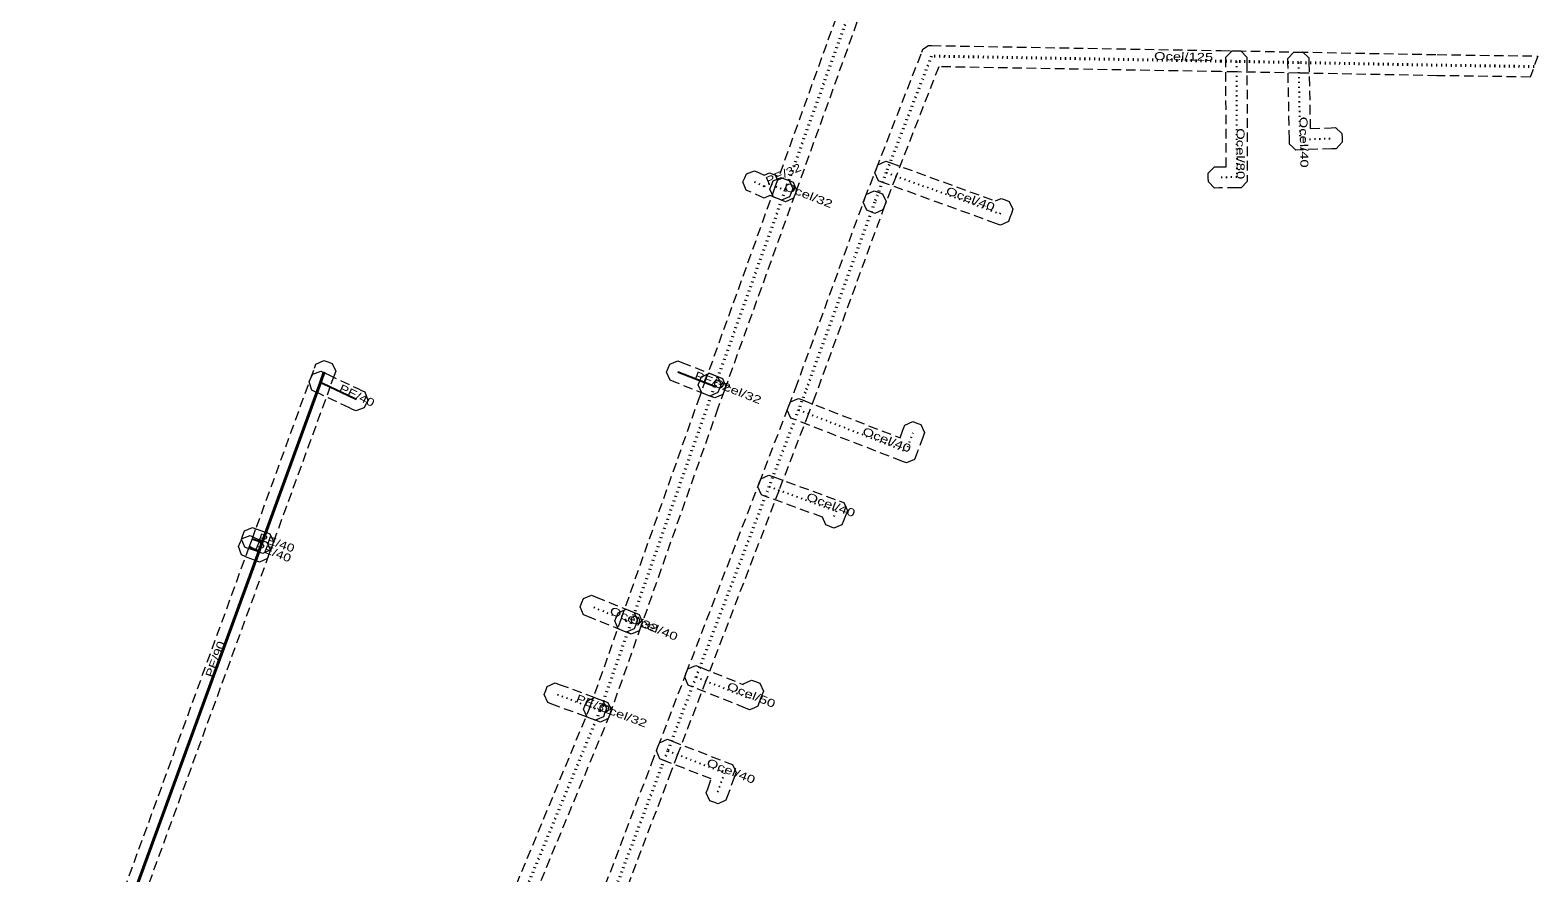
# Model space of a CAD drawing. Extents: x -644301 to -644150, y -1042432 to -1042139.
# Drawn here: x -644293 to -644149.7, y -1042284.7 to -1042204.6 of the extents above; entities that cross this region are included whole.
import ezdxf

# ---------------------------------------------------------------- set-up
doc = ezdxf.new("R2010")
doc.units = 0
doc.header["$LTSCALE"] = 0.3
doc.linetypes.add('DOTTED', pattern=[1.5, 0.3, -1.2])
doc.linetypes.add('MEDIUM_DASHED', pattern=[4.5, 3, -1.5])
for name, color, linetype, lineweight in [('1', 7, 'MEDIUM_DASHED', 13), ('14', 7, 'Continuous', 25), ('18', 7, 'DOTTED', 25)]:
    doc.layers.add(name, color=color, linetype=linetype, lineweight=lineweight)
doc.layers.add('20', color=7, linetype='Continuous')

msp = doc.modelspace()

# ---------------------------------------------------------------- linework, layer by layer
at = {"layer": '1'}
for points in [[(-644250.393, -1042294.532), (-644239.756, -1042268.927), (-644236.811, -1042260.588), (-644229.493, -1042239.868), (-644228.876, -1042238.156), (-644222.16, -1042219.521), (-644214.681, -1042198.769), (-644215.428, -1042198.11), (-644215.739, -1042197.836), (-644215.791, -1042197.01), (-644215.517, -1042196.699), (-644215.243, -1042196.388), (-644214.417, -1042196.336), (-644214.106, -1042196.61), (-644212.849, -1042197.718), (-644212.618, -1042197.921), (-644212.465, -1042198.517), (-644212.569, -1042198.807), (-644220.278, -1042220.199), (-644226.994, -1042238.834), (-644227.609, -1042240.54), (-644234.925, -1042261.254), (-644237.888, -1042269.645), (-644248.531, -1042295.264)], [(-644242.633, -1042297.224), (-644233.926, -1042274.319), (-644233.312, -1042272.722), (-644230.622, -1042265.714), (-644223.677, -1042247.626), (-644220.88, -1042240.342), (-644220.242, -1042238.679), (-644213.656, -1042220.626), (-644213.514, -1042220.237), (-644212.763, -1042219.888), (-644212.374, -1042220.03), (-644211.985, -1042220.172), (-644211.636, -1042220.923), (-644211.778, -1042221.312), (-644218.368, -1042239.381), (-644219.012, -1042241.058), (-644221.809, -1042248.342), (-644228.754, -1042266.43), (-644231.446, -1042273.44), (-644232.058, -1042275.033), (-644240.763, -1042297.934)], [(-644284.943, -1042288.776), (-644272.15, -1042253.741), (-644271.852, -1042252.926), (-644271.454, -1042251.836), (-644266.326, -1042237.765), (-644265.953, -1042236.745), (-644265.811, -1042236.356), (-644265.06, -1042236.007), (-644264.671, -1042236.149), (-644264.282, -1042236.291), (-644263.933, -1042237.042), (-644264.075, -1042237.431), (-644264.446, -1042238.451), (-644269.576, -1042252.522), (-644269.974, -1042253.612), (-644270.272, -1042254.427), (-644283.063, -1042289.46)]]:
    msp.add_lwpolyline(points, dxfattribs=at)
for points in [[(-644159.262, -1042206.963), (-644149.705, -1042207.101), (-644150.422, -1042209.091), (-644159.296, -1042208.963), (-644172.473, -1042208.718), (-644178.366, -1042208.608), (-644179.839, -1042208.581), (-644206.639, -1042208.116), (-644210.689, -1042218.518), (-644211.785, -1042221.332), (-644211.935, -1042221.718), (-644212.694, -1042222.051), (-644213.08, -1042221.901), (-644213.466, -1042221.751), (-644213.799, -1042220.992), (-644213.649, -1042220.606), (-644212.553, -1042217.792), (-644208.25, -1042206.741), (-644208.136, -1042206.448), (-644207.615, -1042206.099), (-644207.301, -1042206.104), (-644179.803, -1042206.581), (-644178.33, -1042206.608), (-644172.435, -1042206.718)], [(-644177.349, -1042207.191), (-644177.348, -1042207.605), (-644177.317, -1042218.605), (-644177.316, -1042219.017), (-644177.893, -1042219.603), (-644178.305, -1042219.608), (-644180.004, -1042219.629), (-644180.418, -1042219.634), (-644181.011, -1042219.055), (-644181.016, -1042218.641), (-644181.021, -1042218.227), (-644180.442, -1042217.634), (-644180.028, -1042217.629), (-644179.32, -1042217.62), (-644179.348, -1042207.611), (-644179.349, -1042207.197), (-644178.765, -1042206.609), (-644178.351, -1042206.608), (-644177.937, -1042206.607)], [(-644171.462, -1042207.284), (-644171.454, -1042207.698), (-644171.331, -1042213.982), (-644169.341, -1042213.914), (-644168.927, -1042213.9), (-644168.321, -1042214.464), (-644168.307, -1042214.878), (-644168.293, -1042215.292), (-644168.857, -1042215.898), (-644169.271, -1042215.912), (-644172.276, -1042216.016), (-644172.695, -1042216.031), (-644172.999, -1042215.743), (-644173.303, -1042215.455), (-644173.311, -1042215.037), (-644173.454, -1042207.738), (-644173.462, -1042207.324), (-644172.888, -1042206.726), (-644172.474, -1042206.718), (-644172.06, -1042206.71)], [(-644221.571, -1042220.797), (-644221.957, -1042220.645), (-644222.69, -1042220.356), (-644223.22, -1042220.584), (-644224.556, -1042219.998), (-644224.935, -1042219.831), (-644225.237, -1042219.059), (-644225.07, -1042218.68), (-644224.903, -1042218.301), (-644224.131, -1042217.999), (-644223.752, -1042218.166), (-644223.212, -1042218.404), (-644222.724, -1042218.194), (-644221.225, -1042218.783), (-644220.839, -1042218.935), (-644220.508, -1042219.694), (-644220.66, -1042220.08), (-644220.812, -1042220.466)], [(-644211.28, -1042217.215), (-644201.245, -1042220.86), (-644200.709, -1042220.614), (-644200.321, -1042220.759), (-644199.932, -1042220.903), (-644199.587, -1042221.656), (-644199.732, -1042222.044), (-644199.875, -1042222.429), (-644200.018, -1042222.815), (-644200.766, -1042223.162), (-644201.153, -1042223.021), (-644211.962, -1042219.095), (-644212.351, -1042218.954), (-644212.702, -1042218.203), (-644212.561, -1042217.814), (-644212.42, -1042217.425), (-644211.669, -1042217.074)], [(-644221.198, -1042220.942), (-644221.584, -1042220.791), (-644221.956, -1042220.645), (-644222.342, -1042220.494), (-644222.673, -1042219.735), (-644222.522, -1042219.349), (-644222.371, -1042218.963), (-644221.612, -1042218.632), (-644221.226, -1042218.783), (-644220.854, -1042218.929), (-644220.468, -1042219.08), (-644220.137, -1042219.839), (-644220.288, -1042220.225), (-644220.439, -1042220.611)], [(-644228.383, -1042239.394), (-644228.768, -1042239.242), (-644231.778, -1042238.051), (-644232.163, -1042237.899), (-644232.492, -1042237.138), (-644232.34, -1042236.753), (-644232.188, -1042236.368), (-644231.427, -1042236.039), (-644231.042, -1042236.191), (-644228.032, -1042237.382), (-644227.647, -1042237.534), (-644227.318, -1042238.295), (-644227.47, -1042238.68), (-644227.622, -1042239.065)], [(-644262.013, -1042240.808), (-644262.388, -1042240.633), (-644262.618, -1042240.526), (-644265.557, -1042239.134), (-644265.815, -1042239.011), (-644266.189, -1042238.834), (-644266.467, -1042238.053), (-644266.289, -1042237.679), (-644266.112, -1042237.305), (-644265.331, -1042237.027), (-644264.957, -1042237.205), (-644264.701, -1042237.326), (-644261.766, -1042238.716), (-644261.542, -1042238.821), (-644261.167, -1042238.996), (-644260.884, -1042239.775), (-644261.059, -1042240.15), (-644261.234, -1042240.525)], [(-644227.916, -1042239.578), (-644228.301, -1042239.426), (-644228.766, -1042239.243), (-644229.152, -1042239.091), (-644229.483, -1042238.331), (-644229.331, -1042237.946), (-644229.179, -1042237.56), (-644228.419, -1042237.229), (-644228.034, -1042237.381), (-644227.569, -1042237.564), (-644227.183, -1042237.716), (-644226.852, -1042238.476), (-644227.004, -1042238.861), (-644227.156, -1042239.247)], [(-644219.97, -1042239.618), (-644219.584, -1042239.768), (-644210.306, -1042243.367), (-644210.001, -1042242.551), (-644209.856, -1042242.163), (-644209.102, -1042241.819), (-644208.714, -1042241.964), (-644208.326, -1042242.109), (-644207.982, -1042242.863), (-644208.127, -1042243.251), (-644208.786, -1042245.016), (-644208.932, -1042245.407), (-644209.314, -1042245.578), (-644209.695, -1042245.749), (-644210.085, -1042245.598), (-644220.308, -1042241.632), (-644220.694, -1042241.482), (-644221.028, -1042240.724), (-644220.878, -1042240.338), (-644220.728, -1042239.952)], [(-644217.366, -1042251.629), (-644217.671, -1042250.902), (-644223.086, -1042248.923), (-644223.475, -1042248.781), (-644223.824, -1042248.03), (-644223.682, -1042247.641), (-644223.54, -1042247.252), (-644222.789, -1042246.903), (-644222.4, -1042247.045), (-644216.036, -1042249.371), (-644215.636, -1042249.517), (-644215.464, -1042249.906), (-644215.292, -1042250.295), (-644215.453, -1042250.689), (-644215.678, -1042251.239), (-644215.835, -1042251.622), (-644216.599, -1042251.943), (-644216.983, -1042251.786)], [(-644271.829, -1042251.878), (-644271.444, -1042252.03), (-644271.42, -1042252.04), (-644270.693, -1042252.286), (-644270.576, -1042252.327), (-644270.186, -1042252.467), (-644269.832, -1042253.216), (-644269.971, -1042253.606), (-644270.111, -1042253.996), (-644270.86, -1042254.35), (-644271.25, -1042254.211), (-644271.351, -1042254.174), (-644272.108, -1042253.918), (-644272.18, -1042253.89), (-644272.565, -1042253.738), (-644272.894, -1042252.977), (-644272.742, -1042252.592), (-644272.59, -1042252.207)], [(-644272.049, -1042252.648), (-644271.674, -1042252.823), (-644271.551, -1042252.88), (-644270.936, -1042253.12), (-644270.869, -1042253.144), (-644270.48, -1042253.286), (-644270.129, -1042254.037), (-644270.271, -1042254.426), (-644270.413, -1042254.815), (-644271.164, -1042255.166), (-644271.553, -1042255.024), (-644271.64, -1042254.992), (-644272.339, -1042254.72), (-644272.52, -1042254.635), (-644272.895, -1042254.46), (-644273.178, -1042253.681), (-644273.003, -1042253.306), (-644272.828, -1042252.931)], [(-644236.325, -1042261.815), (-644236.709, -1042261.658), (-644239.988, -1042260.32), (-644240.372, -1042260.163), (-644240.693, -1042259.4), (-644240.536, -1042259.016), (-644240.379, -1042258.632), (-644239.616, -1042258.311), (-644239.232, -1042258.468), (-644235.953, -1042259.806), (-644235.569, -1042259.963), (-644235.248, -1042260.726), (-644235.405, -1042261.11), (-644235.562, -1042261.494)], [(-644236.337, -1042259.649), (-644235.953, -1042259.806), (-644235.49, -1042259.995), (-644235.106, -1042260.152), (-644234.785, -1042260.915), (-644234.942, -1042261.299), (-644235.099, -1042261.683), (-644235.862, -1042262.004), (-644236.246, -1042261.847), (-644236.709, -1042261.658), (-644237.093, -1042261.501), (-644237.414, -1042260.738), (-644237.257, -1042260.354), (-644237.1, -1042259.97)], [(-644229.315, -1042265.144), (-644225.203, -1042266.798), (-644225.175, -1042266.723), (-644224.423, -1042266.376), (-644224.034, -1042266.518), (-644223.645, -1042266.661), (-644223.298, -1042267.413), (-644223.44, -1042267.802), (-644223.68, -1042268.456), (-644223.826, -1042268.853), (-644224.213, -1042269.025), (-644224.6, -1042269.197), (-644224.992, -1042269.039), (-644230.061, -1042267), (-644230.445, -1042266.845), (-644230.771, -1042266.083), (-644230.616, -1042265.699), (-644230.461, -1042265.315), (-644229.699, -1042264.989)], [(-644239.253, -1042270.193), (-644239.641, -1042270.048), (-644240.109, -1042269.873), (-644243.388, -1042268.652), (-644243.776, -1042268.507), (-644244.121, -1042267.754), (-644243.976, -1042267.366), (-644243.831, -1042266.978), (-644243.078, -1042266.633), (-644242.69, -1042266.778), (-644239.411, -1042267.999), (-644238.941, -1042268.174), (-644238.553, -1042268.319), (-644238.209, -1042269.073), (-644238.354, -1042269.461), (-644238.499, -1042269.849)], [(-644238.784, -1042270.368), (-644239.172, -1042270.223), (-644239.641, -1042270.048), (-644240.029, -1042269.903), (-644240.373, -1042269.149), (-644240.228, -1042268.761), (-644240.083, -1042268.373), (-644239.329, -1042268.029), (-644238.941, -1042268.174), (-644238.472, -1042268.349), (-644238.084, -1042268.494), (-644237.74, -1042269.248), (-644237.885, -1042269.636), (-644238.03, -1042270.024)], [(-644232.402, -1042271.999), (-644232.016, -1042272.149), (-644226.611, -1042274.252), (-644226.231, -1042274.4), (-644225.895, -1042275.144), (-644226.035, -1042275.527), (-644226.71, -1042277.378), (-644226.852, -1042277.767), (-644227.603, -1042278.116), (-644227.992, -1042277.974), (-644228.381, -1042277.832), (-644228.73, -1042277.081), (-644228.588, -1042276.692), (-644228.249, -1042275.761), (-644232.742, -1042274.013), (-644233.128, -1042273.863), (-644233.461, -1042273.104), (-644233.311, -1042272.718), (-644233.161, -1042272.332)]]:
    msp.add_lwpolyline(points, close=True, dxfattribs=at)
at = {"layer": '14'}
for p, q in [((-644228.4, -1042238.312), (-644231.41, -1042237.121)), ((-644227.935, -1042238.495), (-644228.4, -1042238.312))]:
    msp.add_line(p, q, dxfattribs=at)
at = {"layer": '14', "lineweight": 40}
msp.add_lwpolyline([(-644286.608, -1042295.258), (-644284.279, -1042289.879), (-644284.003, -1042289.118), (-644271.211, -1042254.084), (-644270.913, -1042253.269), (-644270.515, -1042252.179), (-644265.386, -1042238.108), (-644265.014, -1042237.088)], dxfattribs=at)
at = {"layer": '14'}
for points in [[(-644261.965, -1042239.727), (-644262.192, -1042239.621), (-644265.129, -1042238.23), (-644265.386, -1042238.108)], [(-644272.097, -1042253.729), (-644271.945, -1042253.8), (-644271.288, -1042254.056), (-644271.211, -1042254.084)], [(-644271.812, -1042252.96), (-644271.764, -1042252.979), (-644271.022, -1042253.23), (-644270.913, -1042253.269)]]:
    msp.add_lwpolyline(points, dxfattribs=at)
at = {"layer": '18'}
for p, q in [((-644221.219, -1042219.86), (-644221.591, -1042219.714)), ((-644236.331, -1042260.732), (-644239.61, -1042259.394)), ((-644236.331, -1042260.732), (-644235.868, -1042260.921)), ((-644238.822, -1042269.286), (-644239.291, -1042269.111))]:
    msp.add_line(p, q, dxfattribs=at)
at = {"layer": '18', "lineweight": 40}
for points in [[(-644214.767, -1042197.36), (-644213.51, -1042198.468), (-644221.219, -1042219.86), (-644227.935, -1042238.495), (-644228.551, -1042240.204), (-644235.868, -1042260.921), (-644238.822, -1042269.286), (-644249.462, -1042294.898), (-644253.663, -1042306.177), (-644265.37, -1042336.505), (-644273.598, -1042358.025), (-644285.881, -1042390.152), (-644286.759, -1042395.281), (-644289.198, -1042409.522), (-644292.966, -1042431.522)], [(-644150.063, -1042208.096), (-644159.279, -1042207.963), (-644172.454, -1042207.718), (-644178.348, -1042207.608), (-644179.821, -1042207.581), (-644207.318, -1042207.104), (-644211.621, -1042218.155), (-644212.717, -1042220.969)], [(-644212.717, -1042220.969), (-644219.305, -1042239.03), (-644219.946, -1042240.7), (-644222.743, -1042247.984), (-644229.688, -1042266.072), (-644232.379, -1042273.081), (-644232.992, -1042274.676), (-644241.698, -1042297.579), (-644242.274, -1042299.095), (-644244.78, -1042305.687), (-644253.829, -1042329.493), (-644255.179, -1042333.045), (-644255.896, -1042334.931), (-644261.103, -1042348.629), (-644266.297, -1042362.291), (-644266.916, -1042363.921), (-644275.457, -1042385.718), (-644275.954, -1042387.015), (-644280.117, -1042397.883), (-644281.39, -1042401.206)]]:
    msp.add_lwpolyline(points, dxfattribs=at)
at = {"layer": '18'}
for points in [[(-644178.348, -1042207.608), (-644178.317, -1042218.608), (-644180.016, -1042218.629)], [(-644172.454, -1042207.718), (-644172.311, -1042215.017), (-644169.306, -1042214.913)], [(-644221.591, -1042219.714), (-644222.707, -1042219.275), (-644223.216, -1042219.494), (-644224.154, -1042219.082)], [(-644211.621, -1042218.155), (-644200.812, -1042222.081), (-644200.669, -1042221.696)], [(-644219.946, -1042240.7), (-644209.723, -1042244.666), (-644209.064, -1042242.901)], [(-644222.743, -1042247.984), (-644216.379, -1042250.31), (-644216.604, -1042250.86)], [(-644229.688, -1042266.072), (-644224.619, -1042268.111), (-644224.379, -1042267.457)], [(-644239.291, -1042269.111), (-644239.76, -1042268.936), (-644243.039, -1042267.715)], [(-644232.379, -1042273.081), (-644226.974, -1042275.184), (-644227.649, -1042277.035)]]:
    msp.add_lwpolyline(points, dxfattribs=at)

# ---------------------------------------------------------------- texts
at = {"layer": '20'}
for s, rotation, width, p in [('Ocel/125', 359.006, 1.4, (-644186.179, -1042207.471)), ('Ocel/40', 271.122, 1.4, (-644172.353, -1042212.87)), ('Ocel/80', 270.161, 1.4, (-644178.33, -1042213.957)), ('PE/32', 23.28, 1.3, (-644222.881, -1042219.35)), ('Ocel/32', 338.571, 1.4, (-644221.405, -1042219.787)), ('Ocel/40', 340.038, 1.4, (-644206.023, -1042220.188)), ('PE/32', 338.412, 1.3, (-644229.905, -1042237.716)), ('Ocel/32', 338.518, 1.4, (-644228.167, -1042238.403)), ('PE/40', 334.657, 1.3, (-644263.676, -1042238.918)), ('Ocel/40', 338.796, 1.4, (-644213.956, -1042243.024)), ('Ocel/40', 339.923, 1.4, (-644219.282, -1042249.249)), ('PE/40', 338.712, 1.3, (-644271.656, -1042253.912)), ('PE/40', 341.311, 1.3, (-644271.362, -1042253.115)), ('Ocel/32', 337.802, 1.4, (-644237.97, -1042260.063)), ('Ocel/40', 337.794, 1.4, (-644236.099, -1042260.826)), ('PE/90', 69.941, 1.3, (-644275.632, -1042266.19)), ('Ocel/50', 338.088, 1.4, (-644226.83, -1042267.221)), ('PE/32', 339.576, 1.3, (-644241.165, -1042268.413)), ('Ocel/32', 339.538, 1.4, (-644239.056, -1042269.198)), ('Ocel/40', 338.74, 1.4, (-644228.758, -1042274.49))]:
    msp.add_text(s, height=0.75, rotation=rotation, dxfattribs=dict(at, width=width)).set_placement(p)

doc.saveas('drawing.dxf')
